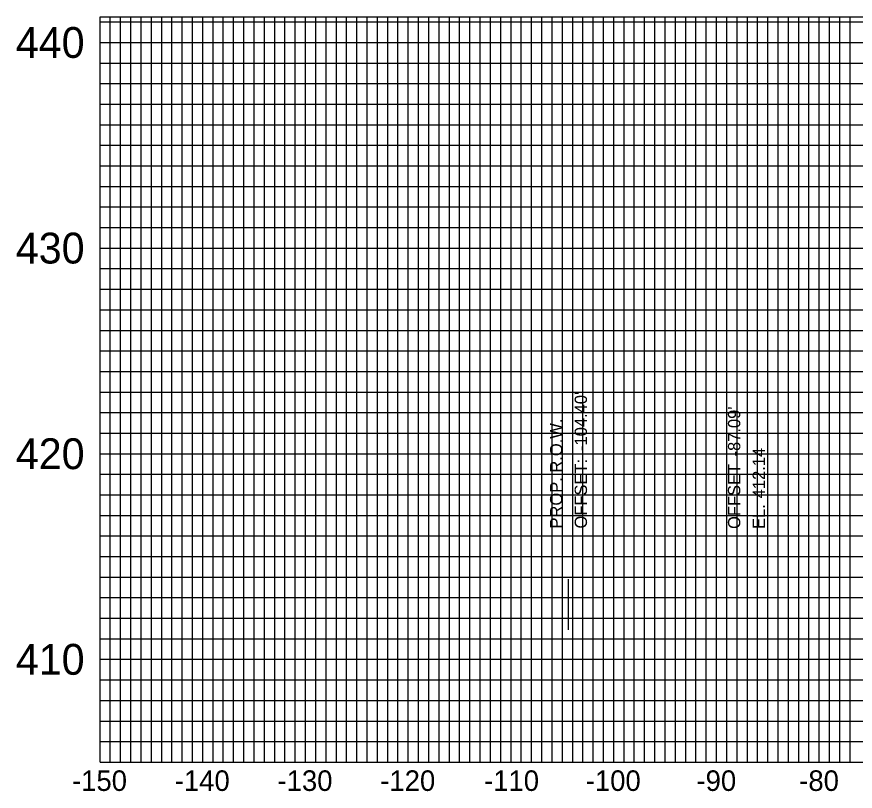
# Model space of a CAD drawing. Extents: x -158 to 158, y 398 to 482.
# Drawn here: x -158.1 to -76.5, y 402.2 to 477.5 of the extents above; entities that cross this region are included whole.
import ezdxf

# ---------------------------------------------------------------- set-up
doc = ezdxf.new("R2010")
doc.units = 0
for name, color, linetype in [('DES - CL - Proposed', 7, 'Continuous'), ('DES - CL - Proposed Text', 7, 'Continuous'), ('DES - SCRATCH - User 1', 7, 'Continuous'), ('DES - SHEET - Corner Text', 7, 'Continuous'), ('DES - SHEET - Revision Text', 7, 'Continuous')]:
    doc.layers.add(name, color=color, linetype=linetype)

msp = doc.modelspace()

# ---------------------------------------------------------------- linework, layer by layer
at = {"layer": 'DES - CL - Proposed'}
msp.add_line((-104.405, 417.881), (-104.405, 422.801), dxfattribs=at)
msp.add_line((-104.405, 417.881), (-104.405, 422.801), dxfattribs=at)
msp.add_line((-104.405, 417.881), (-104.405, 422.801), dxfattribs=at)
msp.add_line((-104.405, 417.881), (-104.405, 422.801), dxfattribs=at)
msp.add_line((-104.405, 417.881), (-104.405, 422.801), dxfattribs=at)
msp.add_line((-104.405, 417.881), (-104.405, 422.801), dxfattribs=at)
at = {"layer": 'DES - SCRATCH - User 1'}
for p, q in [((-150, 477.499), (150, 477.499)), ((-150, 405), (-150, 477.499)), ((-150, 477.499), (150, 477.499)), ((-150, 405), (-150, 477.499)), ((-150, 477.499), (150, 477.499)), ((-150, 405), (-150, 477.499)), ((-140, 405), (-140, 477.499)), ((-140, 405), (-140, 477.499)), ((-140, 405), (-140, 477.499)), ((-130, 405), (-130, 477.499)), ((-130, 405), (-130, 477.499)), ((-130, 405), (-130, 477.499)), ((-120, 405), (-120, 477.499)), ((-120, 405), (-120, 477.499)), ((-120, 405), (-120, 477.499)), ((-110, 405), (-110, 477.499)), ((-110, 405), (-110, 477.499)), ((-110, 405), (-110, 477.499)), ((-100, 405), (-100, 477.499)), ((-100, 405), (-100, 477.499)), ((-100, 405), (-100, 477.499)), ((-90, 405), (-90, 477.499)), ((-90, 405), (-90, 477.499)), ((-90, 405), (-90, 477.499)), ((-80, 405), (-80, 477.499)), ((-80, 405), (-80, 477.499)), ((-80, 405), (-80, 477.499)), ((-150, 475), (150, 475)), ((-150, 475), (150, 475)), ((-150, 475), (150, 475)), ((-150, 455), (150, 455)), ((-150, 455), (150, 455)), ((-150, 455), (150, 455)), ((-150, 435), (150, 435)), ((-150, 435), (150, 435)), ((-150, 435), (150, 435)), ((-150, 415), (150, 415)), ((-150, 415), (150, 415)), ((-150, 415), (150, 415)), ((-150, 405), (150, 405)), ((-150, 405), (150, 405)), ((-150, 405), (150, 405))]:
    msp.add_line(p, q, dxfattribs=at)
at = {"layer": 'DES - SHEET - Corner Text'}
for p, q in [((-149, 405), (-149, 477.499)), ((-149, 405), (-149, 477.499)), ((-149, 405), (-149, 477.499)), ((-148, 405), (-148, 477.499)), ((-148, 405), (-148, 477.499)), ((-148, 405), (-148, 477.499)), ((-147, 405), (-147, 477.499)), ((-147, 405), (-147, 477.499)), ((-147, 405), (-147, 477.499)), ((-146, 405), (-146, 477.499)), ((-146, 405), (-146, 477.499)), ((-146, 405), (-146, 477.499)), ((-145, 405), (-145, 477.499)), ((-145, 405), (-145, 477.499)), ((-145, 405), (-145, 477.499)), ((-144, 405), (-144, 477.499)), ((-144, 405), (-144, 477.499)), ((-144, 405), (-144, 477.499)), ((-143, 405), (-143, 477.499)), ((-143, 405), (-143, 477.499)), ((-143, 405), (-143, 477.499)), ((-142, 405), (-142, 477.499)), ((-142, 405), (-142, 477.499)), ((-142, 405), (-142, 477.499)), ((-141, 405), (-141, 477.499)), ((-141, 405), (-141, 477.499)), ((-141, 405), (-141, 477.499)), ((-139, 405), (-139, 477.499)), ((-139, 405), (-139, 477.499)), ((-139, 405), (-139, 477.499)), ((-138, 405), (-138, 477.499)), ((-138, 405), (-138, 477.499)), ((-138, 405), (-138, 477.499)), ((-137, 405), (-137, 477.499)), ((-137, 405), (-137, 477.499)), ((-137, 405), (-137, 477.499)), ((-136, 405), (-136, 477.499)), ((-136, 405), (-136, 477.499)), ((-136, 405), (-136, 477.499)), ((-135, 405), (-135, 477.499)), ((-135, 405), (-135, 477.499)), ((-135, 405), (-135, 477.499)), ((-134, 405), (-134, 477.499)), ((-134, 405), (-134, 477.499)), ((-134, 405), (-134, 477.499)), ((-133, 405), (-133, 477.499)), ((-133, 405), (-133, 477.499)), ((-133, 405), (-133, 477.499)), ((-132, 405), (-132, 477.499)), ((-132, 405), (-132, 477.499)), ((-132, 405), (-132, 477.499)), ((-131, 405), (-131, 477.499)), ((-131, 405), (-131, 477.499)), ((-131, 405), (-131, 477.499)), ((-129, 405), (-129, 477.499)), ((-129, 405), (-129, 477.499)), ((-129, 405), (-129, 477.499)), ((-128, 405), (-128, 477.499)), ((-128, 405), (-128, 477.499)), ((-128, 405), (-128, 477.499)), ((-127, 405), (-127, 477.499)), ((-127, 405), (-127, 477.499)), ((-127, 405), (-127, 477.499)), ((-126, 405), (-126, 477.499)), ((-126, 405), (-126, 477.499)), ((-126, 405), (-126, 477.499)), ((-125, 405), (-125, 477.499)), ((-125, 405), (-125, 477.499)), ((-125, 405), (-125, 477.499)), ((-124, 405), (-124, 477.499)), ((-124, 405), (-124, 477.499)), ((-124, 405), (-124, 477.499)), ((-123, 405), (-123, 477.499)), ((-123, 405), (-123, 477.499)), ((-123, 405), (-123, 477.499)), ((-122, 405), (-122, 477.499)), ((-122, 405), (-122, 477.499)), ((-122, 405), (-122, 477.499)), ((-121, 405), (-121, 477.499)), ((-121, 405), (-121, 477.499)), ((-121, 405), (-121, 477.499)), ((-119, 405), (-119, 477.499)), ((-119, 405), (-119, 477.499)), ((-119, 405), (-119, 477.499)), ((-118, 405), (-118, 477.499)), ((-118, 405), (-118, 477.499)), ((-118, 405), (-118, 477.499)), ((-117, 405), (-117, 477.499)), ((-117, 405), (-117, 477.499)), ((-117, 405), (-117, 477.499)), ((-116, 405), (-116, 477.499)), ((-116, 405), (-116, 477.499)), ((-116, 405), (-116, 477.499)), ((-115, 405), (-115, 477.499)), ((-115, 405), (-115, 477.499)), ((-115, 405), (-115, 477.499)), ((-114, 405), (-114, 477.499)), ((-114, 405), (-114, 477.499)), ((-114, 405), (-114, 477.499)), ((-113, 405), (-113, 477.499)), ((-113, 405), (-113, 477.499)), ((-113, 405), (-113, 477.499)), ((-112, 405), (-112, 477.499)), ((-112, 405), (-112, 477.499)), ((-112, 405), (-112, 477.499)), ((-111, 405), (-111, 477.499)), ((-111, 405), (-111, 477.499)), ((-111, 405), (-111, 477.499)), ((-109, 405), (-109, 477.499)), ((-109, 405), (-109, 477.499)), ((-109, 405), (-109, 477.499)), ((-108, 405), (-108, 477.499)), ((-108, 405), (-108, 477.499)), ((-108, 405), (-108, 477.499)), ((-107, 405), (-107, 477.499)), ((-107, 405), (-107, 477.499)), ((-107, 405), (-107, 477.499)), ((-106, 405), (-106, 477.499)), ((-106, 405), (-106, 477.499)), ((-106, 405), (-106, 477.499)), ((-105, 405), (-105, 477.499)), ((-105, 405), (-105, 477.499)), ((-105, 405), (-105, 477.499)), ((-104, 405), (-104, 477.499)), ((-104, 405), (-104, 477.499)), ((-104, 405), (-104, 477.499)), ((-103, 405), (-103, 477.499)), ((-103, 405), (-103, 477.499)), ((-103, 405), (-103, 477.499)), ((-102, 405), (-102, 477.499)), ((-102, 405), (-102, 477.499)), ((-102, 405), (-102, 477.499)), ((-101, 405), (-101, 477.499)), ((-101, 405), (-101, 477.499)), ((-101, 405), (-101, 477.499)), ((-99, 405), (-99, 477.499)), ((-99, 405), (-99, 477.499)), ((-99, 405), (-99, 477.499)), ((-98, 405), (-98, 477.499)), ((-98, 405), (-98, 477.499)), ((-98, 405), (-98, 477.499)), ((-97, 405), (-97, 477.499)), ((-97, 405), (-97, 477.499)), ((-97, 405), (-97, 477.499)), ((-96, 405), (-96, 477.499)), ((-96, 405), (-96, 477.499)), ((-96, 405), (-96, 477.499)), ((-95, 405), (-95, 477.499)), ((-95, 405), (-95, 477.499)), ((-95, 405), (-95, 477.499)), ((-94, 405), (-94, 477.499)), ((-94, 405), (-94, 477.499)), ((-94, 405), (-94, 477.499)), ((-93, 405), (-93, 477.499)), ((-93, 405), (-93, 477.499)), ((-93, 405), (-93, 477.499)), ((-92, 405), (-92, 477.499)), ((-92, 405), (-92, 477.499)), ((-92, 405), (-92, 477.499)), ((-91, 405), (-91, 477.499)), ((-91, 405), (-91, 477.499)), ((-91, 405), (-91, 477.499)), ((-89, 405), (-89, 477.499)), ((-89, 405), (-89, 477.499)), ((-89, 405), (-89, 477.499)), ((-88, 405), (-88, 477.499)), ((-88, 405), (-88, 477.499)), ((-88, 405), (-88, 477.499)), ((-87, 405), (-87, 477.499)), ((-87, 405), (-87, 477.499)), ((-87, 405), (-87, 477.499)), ((-86, 405), (-86, 477.499)), ((-86, 405), (-86, 477.499)), ((-86, 405), (-86, 477.499)), ((-85, 405), (-85, 477.499)), ((-85, 405), (-85, 477.499)), ((-85, 405), (-85, 477.499)), ((-84, 405), (-84, 477.499)), ((-84, 405), (-84, 477.499)), ((-84, 405), (-84, 477.499)), ((-83, 405), (-83, 477.499)), ((-83, 405), (-83, 477.499)), ((-83, 405), (-83, 477.499)), ((-82, 405), (-82, 477.499)), ((-82, 405), (-82, 477.499)), ((-82, 405), (-82, 477.499)), ((-81, 405), (-81, 477.499)), ((-81, 405), (-81, 477.499)), ((-81, 405), (-81, 477.499)), ((-79, 405), (-79, 477.499)), ((-79, 405), (-79, 477.499)), ((-79, 405), (-79, 477.499)), ((-78, 405), (-78, 477.499)), ((-78, 405), (-78, 477.499)), ((-78, 405), (-78, 477.499)), ((-77, 405), (-77, 477.499)), ((-77, 405), (-77, 477.499)), ((-77, 405), (-77, 477.499)), ((-150, 477), (150, 477)), ((-150, 477), (150, 477)), ((-150, 477), (150, 477)), ((-150, 473), (150, 473)), ((-150, 473), (150, 473)), ((-150, 473), (150, 473)), ((-150, 471), (150, 471)), ((-150, 471), (150, 471)), ((-150, 471), (150, 471)), ((-150, 469), (150, 469)), ((-150, 469), (150, 469)), ((-150, 469), (150, 469)), ((-150, 467), (150, 467)), ((-150, 467), (150, 467)), ((-150, 467), (150, 467)), ((-150, 465), (150, 465)), ((-150, 465), (150, 465)), ((-150, 465), (150, 465)), ((-150, 463), (150, 463)), ((-150, 463), (150, 463)), ((-150, 463), (150, 463)), ((-150, 461), (150, 461)), ((-150, 461), (150, 461)), ((-150, 461), (150, 461)), ((-150, 459), (150, 459)), ((-150, 459), (150, 459)), ((-150, 459), (150, 459)), ((-150, 457), (150, 457)), ((-150, 457), (150, 457)), ((-150, 457), (150, 457)), ((-150, 453), (150, 453)), ((-150, 453), (150, 453)), ((-150, 453), (150, 453)), ((-150, 451), (150, 451)), ((-150, 451), (150, 451)), ((-150, 451), (150, 451)), ((-150, 449), (150, 449)), ((-150, 449), (150, 449)), ((-150, 449), (150, 449)), ((-150, 447), (150, 447)), ((-150, 447), (150, 447)), ((-150, 447), (150, 447)), ((-150, 445), (150, 445)), ((-150, 445), (150, 445)), ((-150, 445), (150, 445)), ((-150, 443), (150, 443)), ((-150, 443), (150, 443)), ((-150, 443), (150, 443)), ((-150, 441), (150, 441)), ((-150, 441), (150, 441)), ((-150, 441), (150, 441)), ((-150, 439), (150, 439)), ((-150, 439), (150, 439)), ((-150, 439), (150, 439)), ((-150, 437), (150, 437)), ((-150, 437), (150, 437)), ((-150, 437), (150, 437)), ((-150, 433), (150, 433)), ((-150, 433), (150, 433)), ((-150, 433), (150, 433)), ((-150, 431), (150, 431)), ((-150, 431), (150, 431)), ((-150, 431), (150, 431)), ((-150, 429), (150, 429)), ((-150, 429), (150, 429)), ((-150, 429), (150, 429)), ((-150, 427), (150, 427)), ((-150, 427), (150, 427)), ((-150, 427), (150, 427)), ((-150, 425), (150, 425)), ((-150, 425), (150, 425)), ((-150, 425), (150, 425)), ((-150, 423), (150, 423)), ((-150, 423), (150, 423)), ((-150, 423), (150, 423)), ((-150, 421), (150, 421)), ((-150, 421), (150, 421)), ((-150, 421), (150, 421)), ((-150, 419), (150, 419)), ((-150, 419), (150, 419)), ((-150, 419), (150, 419)), ((-150, 417), (150, 417)), ((-150, 417), (150, 417)), ((-150, 417), (150, 417)), ((-150, 413), (150, 413)), ((-150, 413), (150, 413)), ((-150, 413), (150, 413)), ((-150, 411), (150, 411)), ((-150, 411), (150, 411)), ((-150, 411), (150, 411)), ((-150, 409), (150, 409)), ((-150, 409), (150, 409)), ((-150, 409), (150, 409)), ((-150, 407), (150, 407)), ((-150, 407), (150, 407)), ((-150, 407), (150, 407))]:
    msp.add_line(p, q, dxfattribs=at)

# ---------------------------------------------------------------- texts
at = {"layer": 'DES - CL - Proposed'}
for s, p in [("-104.40'", (-102.605, 435.267)), ("-104.40'", (-102.605, 435.267)), ("-104.40'", (-102.605, 435.267)), ("-104.40'", (-102.605, 435.267)), ("-104.40'", (-102.605, 435.267)), ("-104.40'", (-102.605, 435.267)), ('PROP. R.O.W.', (-105.005, 427.721)), ('PROP. R.O.W.', (-105.005, 427.721)), ('PROP. R.O.W.', (-105.005, 427.721)), ('PROP. R.O.W.', (-105.005, 427.721)), ('PROP. R.O.W.', (-105.005, 427.721)), ('PROP. R.O.W.', (-105.005, 427.721)), ('OFFSET: ', (-102.605, 427.721)), ('OFFSET: ', (-102.605, 427.721)), ('OFFSET: ', (-102.605, 427.721)), ('OFFSET: ', (-102.605, 427.721)), ('OFFSET: ', (-102.605, 427.721)), ('OFFSET: ', (-102.605, 427.721))]:
    msp.add_text(s, height=1.2, rotation=90, dxfattribs=at).set_placement(p)
at = {"layer": 'DES - CL - Proposed Text'}
for s, p in [("-87.09'", (-87.686, 434.732)), ("-87.09'", (-87.686, 434.732)), ("-87.09'", (-87.686, 434.732)), ('412.14', (-85.286, 430.664)), ('412.14', (-85.286, 430.664)), ('412.14', (-85.286, 430.664)), ('OFFSET ', (-87.686, 427.682)), ('OFFSET ', (-87.686, 427.682)), ('OFFSET ', (-87.686, 427.682)), ('EL. ', (-85.286, 427.682)), ('EL. ', (-85.286, 427.682)), ('EL. ', (-85.286, 427.682))]:
    msp.add_text(s, height=1.2, rotation=90, dxfattribs=at).set_placement(p)
at = {"layer": 'DES - SHEET - Revision Text'}
for s, height, p in [('440', 3, (-158.194, 473.5)), ('440', 3, (-158.194, 473.5)), ('440', 3, (-158.194, 473.5)), ('430', 3, (-158.194, 453.5)), ('430', 3, (-158.194, 453.5)), ('430', 3, (-158.194, 453.5)), ('420', 3, (-158.194, 433.5)), ('420', 3, (-158.194, 433.5)), ('420', 3, (-158.194, 433.5)), ('410', 3, (-158.194, 413.5)), ('410', 3, (-158.194, 413.5)), ('410', 3, (-158.194, 413.5)), ('-150', 2, (-152.728, 402.2)), ('-150', 2, (-152.728, 402.2)), ('-150', 2, (-152.728, 402.2)), ('-140', 2, (-142.728, 402.2)), ('-140', 2, (-142.728, 402.2)), ('-140', 2, (-142.728, 402.2)), ('-130', 2, (-132.728, 402.2)), ('-130', 2, (-132.728, 402.2)), ('-130', 2, (-132.728, 402.2)), ('-120', 2, (-122.728, 402.2)), ('-120', 2, (-122.728, 402.2)), ('-120', 2, (-122.728, 402.2)), ('-110', 2, (-112.624, 402.2)), ('-110', 2, (-112.624, 402.2)), ('-110', 2, (-112.624, 402.2)), ('-100', 2, (-102.728, 402.2)), ('-100', 2, (-102.728, 402.2)), ('-100', 2, (-102.728, 402.2)), ('-90', 2, (-91.951, 402.2)), ('-90', 2, (-91.951, 402.2)), ('-90', 2, (-91.951, 402.2)), ('-80', 2, (-81.951, 402.2)), ('-80', 2, (-81.951, 402.2)), ('-80', 2, (-81.951, 402.2))]:
    msp.add_text(s, height=height, dxfattribs=at).set_placement(p)

doc.saveas('drawing.dxf')
